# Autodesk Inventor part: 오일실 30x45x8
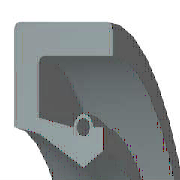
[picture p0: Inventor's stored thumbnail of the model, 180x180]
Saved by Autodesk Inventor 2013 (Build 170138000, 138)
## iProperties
IsCustomPart: 1
Created: 2012-02
Part Number: 오일실 30x45x8
Material: 고무
Document SubType Name: Modeling
Standard: JIS B 2402
Designer: mdu-01
Standards Organization: JIS
Language: ko-KR
Size Designation: 30 45 8 A
Categories: <MemberInstance><Categories><Category DisplayName="샤프트 부품" InternalName="7f7aeb1f-a693-4053-b835-cee3144e0d98" Mnemonic="SHFT"><Category DisplayName="실링" Intern
Density: 0.93 g/cm^3
Author: mdu-01
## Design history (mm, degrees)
body "Solid1"
revolve "회전1" stored, may be unused: angle "d33" = 360 deg
fillet "모깎기1" dims "d34" = 0.4 (= 0.05 x b)
sketch "스케치2"
  geometry: L1 (16.821, -5.895)-(17.526, -8); L2 (16.071, -5.2)-(16.821, -5.895); L3 (15, -2)-(16.071, -5.2); L4 (16, -1)-(15, -2); L5 (17.676, -1)-(16, -1); L6 (17.676, -1.8)-(17.676, -1); L7 (17.676, -6)-(17.676, -3.4); L8 (19.5, -6)-(17.676, -6); L9 (21, -2)-(19.5, -6); L10 (21, 0)-(21, -2); L11 (22.5, 0)-(21, 0); L12 (22.5, -8)-(22.5, 0); L13 (17.526, -8)-(22.5, -8); L14 (0, -9.6)-(0, 1.6) reference; L15 (28, 0)-(14, 0) reference; A1 r 0.8 centre (17.676, -2.6) between (17.676, -3.4) and (17.676, -1.8)
  constraints: 26 end point, 4 horizontal, 4 vertical, 2 point on circle, 1 centre point, 1 collinear, 1 parallel
  dimensions: "d2" = 8 distance of L12.start L11.start (= b); "d4" = 1 vertical distance of L10.start L5.start (= 0.125 x b); "d6" = 1.5 distance of L11.start L10.start (= 0.1 x dd - 0.1 x Diam); "d8" = 2 distance of L10.start L9.start (= 0.25 x b); "d10" = 2 vertical distance of L8.start L1.end (= 0.25 x b); "d12" = 1.5 horizontal distance of L9.start L8.start (= 0.1 x dd - 0.1 x Diam); "d14" = 0.8 radius of A1 (= 0.1 x b); "d16" = 0 horizontal distance of A1.centre L7.end; "d18" = 0.8 distance of L6.start L5.start (= 0.1 x b); "d20" = 1 horizontal distance of L4.start L3.start (= 0.0666667 x dd - 0.0666667 x Diam); "d22" = 0.15 horizontal distance of L7.start L1.end (= 0.01 x dd - 0.01 x Diam); "d24" = 1 horizontal distance of L4.start L3.start (= 0.125 x b); "d26" = 3.2 vertical distance of L3.start L2.start (= 0.4 x b); "d28" = 1.07143 horizontal distance of L3.start L2.start (= 0.0714286 x dd - 0.0714286 x Diam); "d30" = 2.10526 vertical distance of L1.start L1.end (= 0.263158 x b); "d32" = 0.75 horizontal distance of L2.start L1.start (= 0.05 x dd - 0.05 x Diam); "d37" = 0 distance between parallel lines of L15 L11; "d38" = 22.5 distance between parallel lines of L14 L12 (= 0.5 x dd); "d39" = 15 distance from line of L14 L3.start (= 0.5 x Diam)
other parameters: "dd" = 45 [user parameter; used in 7 equation terms], "b" = 8 [user parameter; used in 10 equation terms], "d1" = 8 (derived), "d3" = 1 (derived), "d5" = 2 (derived), "d7" = 2 (derived), "d9" = 2 (derived), "d11" = 2 (derived), "d13" = 0.8 (derived), "d15" = 0 (derived), "d17" = 0.8 (derived), "d19" = 1.33333 (derived), "d21" = 0.2 (derived), "d23" = 1 (derived), "d25" = 3.2 (derived), "d27" = 1.42857 (derived), "d29" = 2.10526 (derived), "d31" = 1 (derived), "d40" = 0
